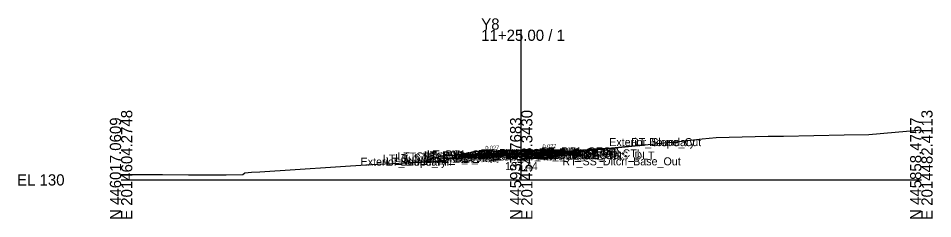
# Model space of a CAD drawing. Extents: x -26 to 1403, y -10 to 8043.
# Drawn here: x -25.7 to 202.8, y 2490.3 to 2540.4 of the extents above; entities that cross this region are included whole.
import ezdxf

# ---------------------------------------------------------------- set-up
doc = ezdxf.new("R2010")
doc.units = 0
for name, color, linetype in [('Default', 7, 'Continuous'), ('Exist Cross Section Cell', 7, 'Continuous'), ('Exist XS Center Line Elevation Label', 7, 'Continuous'), ('Exist XS Ground Line', 7, 'Continuous'), ('Prop CMT Pvmt Course 1', 7, 'Continuous'), ('Prop CMT Pvmt Course 2', 7, 'Continuous'), ('Prop CMT Pvmt Course 3', 7, 'Continuous'), ('Prop CMT Pvmt Surface', 7, 'Continuous'), ('Prop CMT Pvmt Surface Shoulder', 7, 'Continuous'), ('Prop CMT Shld Paved Course 1', 7, 'Continuous'), ('Prop CMT Shld Paved Course 2', 7, 'Continuous'), ('Prop CMT Shld Paved Course 3', 7, 'Continuous'), ('Prop CMT Slope Grass', 7, 'Continuous'), ('Prop CMT Subgrade Earthwork', 7, 'Continuous'), ('Prop XS Earthwork Shape', 7, 'Continuous'), ('Prop XS SE Text', 7, 'Continuous'), ('Prop XS Side Slope Text', 7, 'Continuous'), ('Scratch_Level_0', 7, 'Continuous')]:
    doc.layers.add(name, color=color, linetype=linetype)

msp = doc.modelspace()

# ---------------------------------------------------------------- linework, layer by layer
at = {"layer": 'Exist Cross Section Cell'}
for p, q in [((100, 2500), (100, 2537.54)), ((0, 2500), (100, 2500)), ((100, 2500), (200, 2500))]:
    msp.add_line(p, q, dxfattribs=at)
at = {"layer": 'Exist XS Ground Line'}
msp.add_lwpolyline([(0, 2501.34), (8.95, 2501.38), (10.33, 2501.38), (16.86, 2501.25), (26.3, 2501.29), (30.45, 2501.35), (30.95, 2501.75), (32.56, 2501.93), (34.66, 2502.02), (62.43, 2503.86), (78.25, 2504.6), (79.26, 2504.85), (80.49, 2504.87), (82.7, 2505.32), (83.01, 2505.51), (83.33, 2505.71), (83.97, 2506.15), (85, 2506.49), (86.12, 2506.66), (89.65, 2507.29), (90.2, 2507.39), (91.13, 2507.14), (91.59, 2507.15), (100, 2507.44), (100.75, 2507.47), (102, 2507.44), (111.72, 2507.19), (114.54, 2507.39), (123.85, 2508.11), (130.98, 2508.75), (136.46, 2509.31), (138.11, 2509.47), (140.26, 2509.71), (145.24, 2510.25), (148.71, 2510.62), (161.68, 2510.91), (165.57, 2510.97), (180.69, 2511.3), (186.91, 2511.38), (200, 2512.51)], dxfattribs=at)
at = {"layer": 'Prop CMT Pvmt Course 1'}
for points in [[(100, 2506.74), (114.25, 2507.12)], [(114.25, 2507.12), (114.25, 2506.87)], [(100, 2506.74), (85.68, 2506.35)], [(85.68, 2506.1), (100, 2506.49)], [(85.68, 2506.35), (85.68, 2506.1)], [(114.25, 2506.87), (100, 2506.49)], [(100, 2506.49), (100, 2506.74)], [(100, 2506.49), (100, 2506.74)]]:
    msp.add_lwpolyline(points, dxfattribs=at)
msp.add_lwpolyline([(100, 2506.49), (100, 2506.61), (100, 2506.61), (100, 2506.49)], close=True, dxfattribs=at)
msp.add_lwpolyline([(100, 2506.49), (100, 2506.61), (100, 2506.61), (100, 2506.49)], close=True, dxfattribs=at)
at = {"layer": 'Prop CMT Pvmt Course 2'}
for points in [[(100, 2506.49), (85.68, 2506.1)], [(85.68, 2505.85), (100, 2506.24)], [(85.68, 2506.1), (85.68, 2505.85)], [(100, 2506.49), (114.25, 2506.87)], [(114.25, 2506.62), (100, 2506.24)], [(100, 2506.24), (100, 2506.49)], [(100, 2506.24), (100, 2506.49)], [(114.25, 2506.87), (114.25, 2506.62)]]:
    msp.add_lwpolyline(points, dxfattribs=at)
at = {"layer": 'Prop CMT Pvmt Course 3'}
for points in [[(100, 2506.24), (85.68, 2505.85)], [(85.68, 2505.48), (100, 2505.86)], [(85.68, 2505.85), (85.68, 2505.48)], [(100, 2506.24), (114.25, 2506.62)], [(100, 2505.86), (100, 2506.24)], [(114.25, 2506.24), (100, 2505.86)], [(100, 2505.86), (100, 2506.24)], [(114.25, 2506.62), (114.25, 2506.24)]]:
    msp.add_lwpolyline(points, dxfattribs=at)
at = {"layer": 'Prop CMT Pvmt Surface'}
for points in [[(100, 2506.74), (114.25, 2507.12)], [(100, 2506.74), (85.68, 2506.35)]]:
    msp.add_lwpolyline(points, dxfattribs=at)
at = {"layer": 'Prop CMT Pvmt Surface Shoulder'}
for points in [[(114.25, 2507.12), (114.25, 2507.12)], [(85.68, 2506.35), (85.68, 2506.35)]]:
    msp.add_lwpolyline(points, dxfattribs=at)
at = {"layer": 'Prop CMT Shld Paved Course 1'}
for points in [[(114.25, 2507.12), (114.25, 2507.12)], [(114.25, 2507.12), (114.51, 2506.86)], [(114.25, 2506.87), (114.25, 2507.12)], [(85.68, 2506.35), (85.42, 2506.1)], [(85.42, 2506.1), (85.68, 2506.1)], [(85.68, 2506.35), (85.68, 2506.35)], [(85.68, 2506.1), (85.68, 2506.35)], [(114.51, 2506.86), (114.25, 2506.87)]]:
    msp.add_lwpolyline(points, dxfattribs=at)
at = {"layer": 'Prop CMT Shld Paved Course 2'}
for points in [[(85.68, 2506.1), (85.42, 2506.1), (85.17, 2505.84)], [(85.17, 2505.84), (85.68, 2505.85)], [(85.68, 2505.85), (85.68, 2506.1)], [(114.25, 2506.87), (114.51, 2506.86), (114.76, 2506.61)], [(114.25, 2506.62), (114.25, 2506.87)], [(114.76, 2506.61), (114.25, 2506.62)]]:
    msp.add_lwpolyline(points, dxfattribs=at)
at = {"layer": 'Prop CMT Shld Paved Course 3'}
for points in [[(84.28, 2505.45), (85.68, 2505.48)], [(85.68, 2505.85), (85.17, 2505.84), (84.78, 2505.46)], [(85.68, 2505.48), (85.68, 2505.85)], [(114.25, 2506.24), (114.25, 2506.62)], [(114.25, 2506.62), (114.76, 2506.61), (115.14, 2506.22)], [(115.64, 2506.21), (114.25, 2506.24)]]:
    msp.add_lwpolyline(points, dxfattribs=at)
at = {"layer": 'Prop CMT Slope Grass'}
msp.add_line((114.25, 2507.12), (130.98, 2508.75), dxfattribs=at)
msp.add_lwpolyline([(85.68, 2506.35), (79.68, 2505.87), (75.47, 2504.47)], dxfattribs=at)
at = {"layer": 'Prop CMT Subgrade Earthwork'}
msp.add_line((116.8, 2507.37), (115.64, 2506.21), dxfattribs=at)
for points in [[(84.28, 2505.45), (78.03, 2505.33)], [(85.68, 2505.48), (84.28, 2505.45)], [(100, 2505.86), (85.68, 2505.48)], [(100, 2505.86), (114.25, 2506.24)], [(114.25, 2506.24), (115.64, 2506.21)]]:
    msp.add_lwpolyline(points, dxfattribs=at)
at = {"layer": 'Prop XS Earthwork Shape'}
for points in [[(114.54, 2507.39), (123.85, 2508.11), (130.98, 2508.75), (116.8, 2507.37), (115.64, 2506.21), (114.25, 2506.24), (100, 2505.86), (85.68, 2505.48), (82.87, 2505.42), (83.97, 2506.15), (84.25, 2506.24), (85, 2506.49), (86.12, 2506.66), (89.65, 2507.29), (90.2, 2507.39), (91.13, 2507.14), (91.59, 2507.15), (100, 2507.44), (100.75, 2507.47), (102, 2507.44), (111.72, 2507.19)], [(82.87, 2505.42), (78.03, 2505.33), (75.47, 2504.47), (78.25, 2504.6), (79.26, 2504.85), (80.49, 2504.87), (82.7, 2505.32)]]:
    msp.add_lwpolyline(points, close=True, dxfattribs=at)

# ---------------------------------------------------------------- texts
at = {"layer": 'Default'}
msp.add_text('-', height=0.0001, dxfattribs=at).set_placement((0, 2500))
at = {"layer": 'Exist Cross Section Cell'}
for s, p in [('Y8', (90, 2537.54)), ('11+25.00 / 1', (90, 2534.74)), ('EL 130', (-26, 2498.6))]:
    msp.add_text(s, height=2.8, dxfattribs=at).set_placement(p)
for s, p in [('E 2014604.2748', (2.8, 2490)), ('E 2014543.3430', (102.8, 2490)), ('E 2014482.4113', (202.8, 2490)), ('N 446017.0609', (0, 2490)), ('N 445937.7683', (100, 2490)), ('N 445858.4757', (200, 2490))]:
    msp.add_text(s, height=2.8, rotation=90, dxfattribs=at).set_placement(p)
at = {"layer": 'Exist XS Center Line Elevation Label'}
msp.add_text('137.44', height=2, dxfattribs=at).set_placement((95.96, 2502.44))
at = {"layer": 'Prop XS SE Text'}
for rotation, p in [(1.5297, (91.06, 2507.5)), (1.5299, (105.35, 2507.88))]:
    msp.add_text('0.027', height=1, rotation=rotation, dxfattribs=at).set_placement(p)
at = {"layer": 'Prop XS Side Slope Text'}
msp.add_text('3:1', height=1, rotation=18.4332, dxfattribs=at).set_placement((76.7, 2505.67))
at = {"layer": 'Scratch_Level_0'}
for s, p in [('Exterior Boundary', (121.99, 2508.44)), ('RT_Slope_Cut', (127.44, 2508.44)), ('LT_PS2_OEOP', (75.66, 2505.1)), ('LT_PV2_OEOT', (75.85, 2505.1)), ('LT_PV1_OEOT', (76.42, 2505.35)), ('LT_PS1_OEOP', (76.48, 2505.35)), ('RT_PV2_OEEOP', (89.26, 2505.49)), ('RT_PV3_OEEOP', (89.26, 2505.24)), ('LT_PV2_OEEOP', (89.31, 2505.49)), ('LT_PV3_OEEOP', (89.31, 2505.24)), ('RT_PV1_OEEOP', (89.83, 2505.61)), ('LT_PV1_OEEOP', (89.87, 2505.61)), ('RT_PV2_IEEOP', (89.91, 2505.49)), ('LT_PV2_IEEOP', (89.95, 2505.49)), ('RT_PV1_IEEOP', (90.47, 2505.61)), ('LT_PV1_IEEOP', (90.52, 2505.61)), ('PV2_PGL', (93.91, 2505.49)), ('PV1_PGL', (94.47, 2505.74)), ('RT_Sub_Trench_Out', (99.8, 2505.21)), ('RT_PS3_Shelf_Out', (101.2, 2505.6)), ('RT_Sub_OEOT', (104.28, 2505.24)), ('RT_PV2_OEOT', (104.38, 2505.87)), ('RT_PV3_OEOT', (104.38, 2505.62)), ('RT_PS2_OEOP', (104.7, 2505.86)), ('RT_PV1_OEOT', (104.94, 2506.12)), ('RT_PS3_OEOP', (104.95, 2505.61)), ('RT_PS1_OEOP', (105.01, 2506.12)), ('RT_GS_OS_CTL', (109.57, 2505.64)), ('RT_Sub_OSS_DLT', (109.84, 2505.08)), ('Exterior Boundary', (59.85, 2503.55)), ('LT_Sub_OSS_DLT', (65.44, 2504.33)), ('LT_Slope_Fill', (66.23, 2503.55)), ('LT_Sub_Trench_Out', (68.49, 2504.45)), ('LT_GS_OS_CTL', (69.05, 2504.87)), ('LT_PS3_Shelf_Out', (70.65, 2504.83)), ('LT_PS3_OEOP', (75.4, 2504.84)), ('LT_Sub_OEOT', (75.76, 2504.48)), ('LT_PV3_OEOT', (75.85, 2504.85)), ('RT_Sub_OEEOP', (89.17, 2504.86)), ('LT_Sub_OEEOP', (89.21, 2504.86)), ('RT_SS_Ditch_Base_Out', (110.28, 2503.64))]:
    msp.add_text(s, height=2, dxfattribs=at).set_placement(p)

doc.saveas('drawing.dxf')
